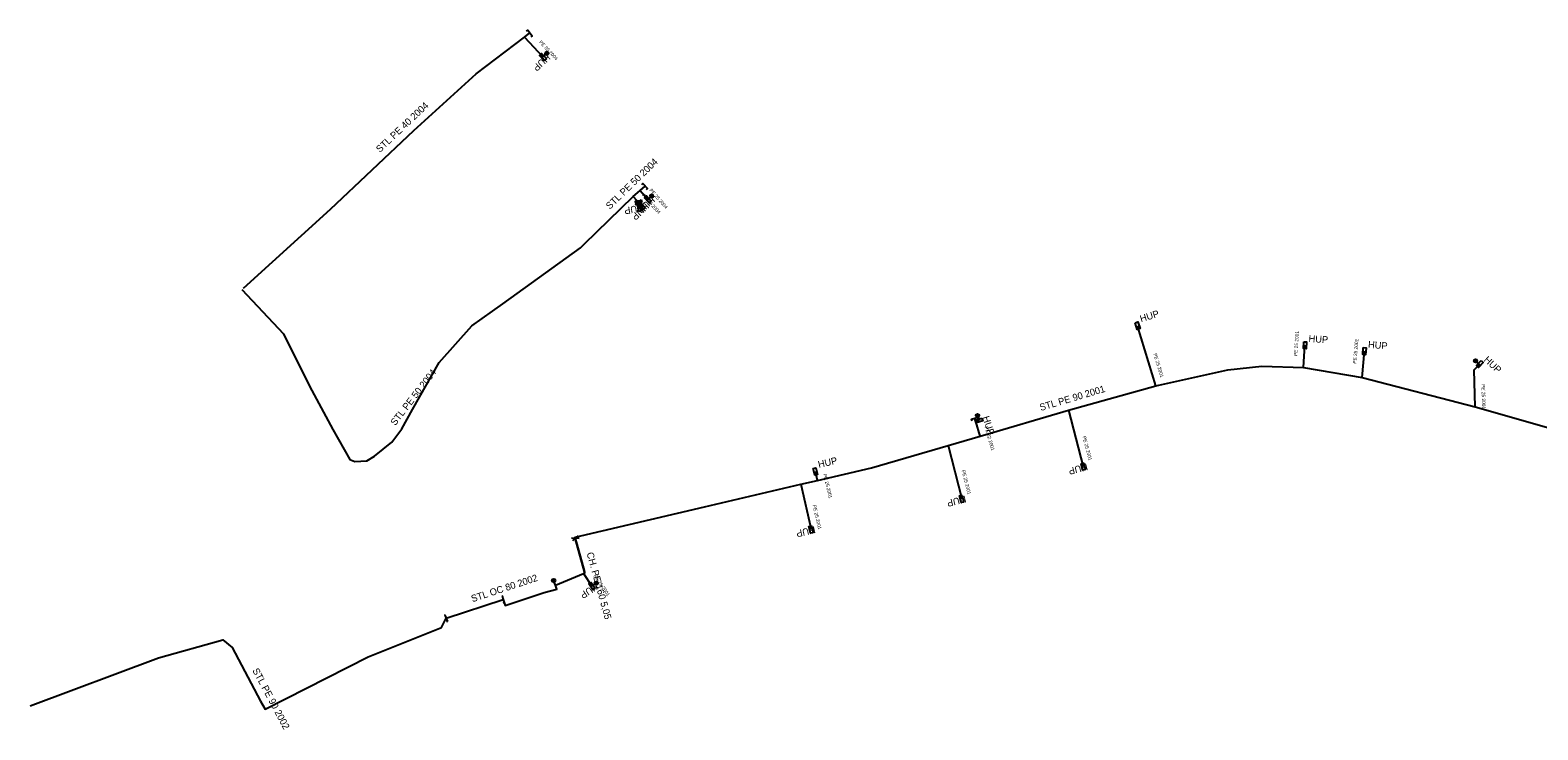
# Model space of a CAD drawing. Extents: x -724831 to -724223, y -1048957 to -1048806.
# Drawn here: x -724831.3 to -724613.1, y -1048928.6 to -1048827.3 of the extents above; entities that cross this region are included whole.
import ezdxf

# ---------------------------------------------------------------- set-up
doc = ezdxf.new("R2010")
doc.units = 0
for name, color, linetype in [('ST OP Chráni_ka - provoz', 7, 'Continuous'), ('ST Úsek p_ípojky - provoz', 7, 'Continuous'), ('ST Úsek plynovodu - provoz', 7, 'Continuous'), ('ST_HUP_22_23_popis', 7, 'Continuous'), ('Vrstva 1', 7, 'Continuous')]:
    doc.layers.add(name, color=color, linetype=linetype)

msp = doc.modelspace()

# ---------------------------------------------------------------- linework, layer by layer
at = {"layer": 'ST OP Chráni_ka - provoz'}
msp.add_lwpolyline([(-724752.41, -1048900.83), (-724751.07, -1048905.68)], dxfattribs=at)
at = {"layer": 'ST Úsek p_ípojky - provoz'}
for points in [[(-724759.77, -1048828.26), (-724757.09, -1048831.14)], [(-724744.01, -1048851.36), (-724743.08, -1048852.4)], [(-724743.03, -1048850.49), (-724741.91, -1048851.77)], [(-724743.08, -1048852.4), (-724743.19, -1048852.5)], [(-724743.19, -1048852.5), (-724743.11, -1048852.97)], [(-724743.08, -1048852.4), (-724742.98, -1048852.52)], [(-724742.98, -1048852.52), (-724742.81, -1048852.7)], [(-724668.37, -1048878.78), (-724671, -1048870.05)], [(-724646.98, -1048876.12), (-724646.78, -1048872.89)], [(-724638.5, -1048877.54), (-724638.18, -1048873.74)], [(-724622.14, -1048881.8), (-724622.26, -1048876.44), (-724621.47, -1048875.59)], [(-724681.03, -1048882.26), (-724678.88, -1048890.46)], [(-724694.42, -1048883.93), (-724694.56, -1048883.45)], [(-724694.42, -1048883.93), (-724693.96, -1048883.79)], [(-724693.82, -1048886.04), (-724694.42, -1048883.93)], [(-724698.43, -1048887.4), (-724696.47, -1048895.14)], [(-724719.78, -1048892.98), (-724718.27, -1048899.58)], [(-724717.34, -1048892.45), (-724717.65, -1048891.15)], [(-724751.23, -1048905.91), (-724750, -1048907.74)]]:
    msp.add_lwpolyline(points, dxfattribs=at)
at = {"layer": 'ST Úsek plynovodu - provoz'}
for points in [[(-724800.46, -1048864.6), (-724787.85, -1048853.16), (-724775.78, -1048841.78), (-724766.76, -1048833.57), (-724759.77, -1048828.26), (-724758.97, -1048827.66)], [(-724751.08, -1048858.22), (-724744.01, -1048851.36), (-724743.03, -1048850.49), (-724742.28, -1048849.83)], [(-724800.68, -1048864.8), (-724794.67, -1048871.23), (-724790.88, -1048878.79), (-724787.5, -1048885.08), (-724785.05, -1048889.44), (-724784.33, -1048889.7), (-724782.59, -1048889.63), (-724781.5, -1048888.92), (-724778.99, -1048886.9), (-724777.51, -1048884.99), (-724775.96, -1048882.19), (-724772.1, -1048875.4), (-724767.41, -1048870.07), (-724762.9, -1048866.87), (-724751.67, -1048858.8), (-724751.08, -1048858.22)], [(-724755.26, -1048907.64), (-724751.23, -1048905.91), (-724751.02, -1048905.85), (-724751.07, -1048905.68), (-724752.41, -1048900.83), (-724752.44, -1048900.67), (-724733.73, -1048896.27), (-724719.78, -1048892.98), (-724717.34, -1048892.45), (-724709.54, -1048890.62), (-724698.43, -1048887.4), (-724693.82, -1048886.04), (-724681.03, -1048882.26), (-724668.37, -1048878.78), (-724657.94, -1048876.45), (-724653.02, -1048875.9), (-724646.98, -1048876.12), (-724638.5, -1048877.54), (-724622.14, -1048881.8), (-724607.06, -1048886.1)], [(-724762.85, -1048909.69), (-724762.58, -1048910.57), (-724756.94, -1048908.7), (-724755.08, -1048908.19), (-724755.26, -1048907.64)], [(-724771.12, -1048912.4), (-724762.85, -1048909.69)], [(-724831.33, -1048925.09), (-724812.73, -1048918.14), (-724803.42, -1048915.54), (-724802.08, -1048916.63), (-724797.96, -1048924.4), (-724797.33, -1048925.59), (-724782.42, -1048918), (-724771.79, -1048913.76), (-724771.12, -1048912.4)]]:
    msp.add_lwpolyline(points, dxfattribs=at)
at = {"layer": 'Vrstva 1'}
for p, q in [((-724757.09, -1048831.14), (-724756.72, -1048830.8)), ((-724741.91, -1048851.77), (-724741.53, -1048851.44)), ((-724621.53, -1048875.65), (-724621.9, -1048875.31)), ((-724693.96, -1048883.79), (-724694.11, -1048883.31)), ((-724751.87, -1048900.86), (-724752.95, -1048900.8)), ((-724752, -1048900.48), (-724752.82, -1048901.18)), ((-724755.26, -1048907.64), (-724755.45, -1048907.17)), ((-724750, -1048907.74), (-724749.58, -1048907.46)), ((-724763, -1048909.21), (-724762.86, -1048909.17)), ((-724763, -1048909.21), (-724762.7, -1048910.17)), ((-724762.7, -1048910.17), (-724762.84, -1048910.21)), ((-724771.32, -1048911.94), (-724771.18, -1048911.88)), ((-724771.32, -1048911.94), (-724770.92, -1048912.86)), ((-724770.92, -1048912.86), (-724771.06, -1048912.92))]:
    msp.add_line(p, q, dxfattribs=at)
for points in [[(-724759.47, -1048827.41), (-724759.27, -1048827.26), (-724758.67, -1048828.06), (-724758.87, -1048828.21)], [(-724742.8, -1048849.62), (-724742.61, -1048849.45), (-724741.95, -1048850.21), (-724742.14, -1048850.37)], [(-724694.97, -1048883.83), (-724695.04, -1048883.59), (-724694.08, -1048883.31), (-724694.01, -1048883.55)]]:
    msp.add_lwpolyline(points, dxfattribs=at)
for points in [[(-724756.6, -1048831.37), (-724756.9, -1048831.64), (-724757.58, -1048830.91), (-724757.28, -1048830.64)], [(-724741.43, -1048852.01), (-724741.73, -1048852.28), (-724742.39, -1048851.53), (-724742.09, -1048851.26)], [(-724742.75, -1048851.94), (-724743.75, -1048852.06), (-724743.13, -1048853)], [(-724742.92, -1048851.82), (-724743.68, -1048852.46), (-724742.66, -1048852.9)], [(-724743.57, -1048852.14), (-724743.16, -1048852.77), (-724742.9, -1048852.06)], [(-724743.5, -1048852.43), (-724742.8, -1048852.73), (-724742.98, -1048852)], [(-724743.18, -1048852.55), (-724743.05, -1048852.18), (-724743.4, -1048852.22)], [(-724742.83, -1048853.43), (-724743.22, -1048853.5), (-724743.39, -1048852.51), (-724743, -1048852.44)], [(-724742.95, -1048852.56), (-724743.04, -1048852.18), (-724743.31, -1048852.4)], [(-724742.32, -1048852.93), (-724742.61, -1048853.2), (-724743.3, -1048852.47), (-724743.01, -1048852.2)], [(-724671.34, -1048869.63), (-724670.95, -1048869.51), (-724670.66, -1048870.47), (-724671.05, -1048870.59)], [(-724646.94, -1048872.38), (-724646.54, -1048872.41), (-724646.61, -1048873.4), (-724647.01, -1048873.37)], [(-724638.33, -1048873.22), (-724637.94, -1048873.26), (-724638.02, -1048874.25), (-724638.42, -1048874.22)], [(-724621.27, -1048875.09), (-724620.98, -1048875.36), (-724621.66, -1048876.09), (-724621.96, -1048875.82)], [(-724693.54, -1048883.45), (-724693.42, -1048883.84), (-724694.38, -1048884.13), (-724694.5, -1048883.74)], [(-724717.96, -1048890.71), (-724717.57, -1048890.62), (-724717.34, -1048891.59), (-724717.73, -1048891.68)], [(-724678.56, -1048890.89), (-724678.94, -1048890.99), (-724679.2, -1048890.03), (-724678.82, -1048889.93)], [(-724696.15, -1048895.58), (-724696.54, -1048895.67), (-724696.78, -1048894.7), (-724696.4, -1048894.61)], [(-724717.96, -1048900.02), (-724718.35, -1048900.11), (-724718.58, -1048899.14), (-724718.19, -1048899.05)], [(-724749.55, -1048908.04), (-724749.89, -1048908.27), (-724750.45, -1048907.44), (-724750.11, -1048907.21)]]:
    msp.add_lwpolyline(points, close=True, dxfattribs=at)
for centre, radius in [((-724756.54, -1048830.62), 0.249), ((-724756.62, -1048830.56), 0.0614), ((-724756.48, -1048830.71), 0.0614), ((-724741.34, -1048851.27), 0.249), ((-724741.42, -1048851.2), 0.0614), ((-724741.29, -1048851.36), 0.0614), ((-724622.08, -1048875.14), 0.249), ((-724622.14, -1048875.23), 0.0614), ((-724622, -1048875.08), 0.0614), ((-724694.18, -1048883.07), 0.249), ((-724694.28, -1048883.11), 0.0614), ((-724694.08, -1048883.05), 0.0614), ((-724755.54, -1048906.94), 0.249), ((-724755.64, -1048906.99), 0.0614), ((-724755.45, -1048906.92), 0.0614), ((-724749.38, -1048907.32), 0.249), ((-724749.45, -1048907.24), 0.0614), ((-724749.33, -1048907.41), 0.0614)]:
    msp.add_circle(centre, radius, dxfattribs=at)

# ---------------------------------------------------------------- texts
at = {"layer": 'ST OP Chráni_ka - provoz'}
msp.add_text('CH. PE 160 5,05', height=1, rotation=285.4418, dxfattribs=at).set_placement((-724750.78, -1048902.99))
at = {"layer": 'ST Úsek p_ípojky - provoz'}
for s, rotation, p in [('PE 25 2004', 312.9399, (-724757.7, -1048829.02)), ('PE 32 2004', 311.8041, (-724742.8, -1048851.21)), ('PE 25 2004', 311.1859, (-724741.72, -1048850.47)), ('PE 25 2001', 86.4391, (-724647.88, -1048874.44)), ('PE 25 2001', 85.1727, (-724639.34, -1048875.56)), ('PE 25 2001', 286.7636, (-724668.73, -1048874.13)), ('PE 25 2001', 271.2825, (-724621.21, -1048878.52)), ('PE 32 2001', 285.8736, (-724693.16, -1048884.71)), ('PE 25 2001', 284.6985, (-724678.99, -1048886.11)), ('PE 25 2001', 284.2172, (-724696.48, -1048891.02)), ('PE 25 2001', 283.4024, (-724716.52, -1048891.57)), ('PE 25 2001', 282.895, (-724718.05, -1048896.06)), ('PE 25 2001', 303.9063, (-724749.79, -1048906.27))]:
    msp.add_text(s, height=0.5, rotation=rotation, dxfattribs=at).set_placement(p)
at = {"layer": 'ST Úsek plynovodu - provoz'}
for s, rotation, p in [('STL PE 40 2004', 43.3146, (-724780.7, -1048845.04)), ('STL PE 50 2004', 44.165, (-724747.41, -1048853.27)), ('STL PE 50 2004', 52.229, (-724778.47, -1048884.59)), ('STL PE 90 2001', 16.4647, (-724685.03, -1048882.4)), ('STL OC 80 2002', 18.1435, (-724767.3, -1048910.09)), ('STL PE 90 2002', 297.9345, (-724799.19, -1048919.95))]:
    msp.add_text(s, height=1, rotation=rotation, dxfattribs=at).set_placement(p)
at = {"layer": 'ST_HUP_22_23_popis'}
for rotation, p in [(223, (-724756.59, -1048830.64)), (221.19, (-724741.41, -1048851.27)), (189.66, (-724742.61, -1048852.47)), (223.36, (-724742.31, -1048852.2)), (17, (-724670.5, -1048869.55)), (356, (-724646.28, -1048872.39)), (355, (-724637.68, -1048873.24)), (317, (-724620.97, -1048875.09)), (287, (-724693.46, -1048883.29)), (13, (-724717.15, -1048890.65)), (195, (-724678.38, -1048889.96)), (194, (-724695.97, -1048894.64)), (193, (-724717.77, -1048899.08)), (214, (-724749.5, -1048907.24))]:
    msp.add_text('HUP', height=1, rotation=rotation, dxfattribs=at).set_placement(p)

doc.saveas('drawing.dxf')
